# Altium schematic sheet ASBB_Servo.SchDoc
size A4
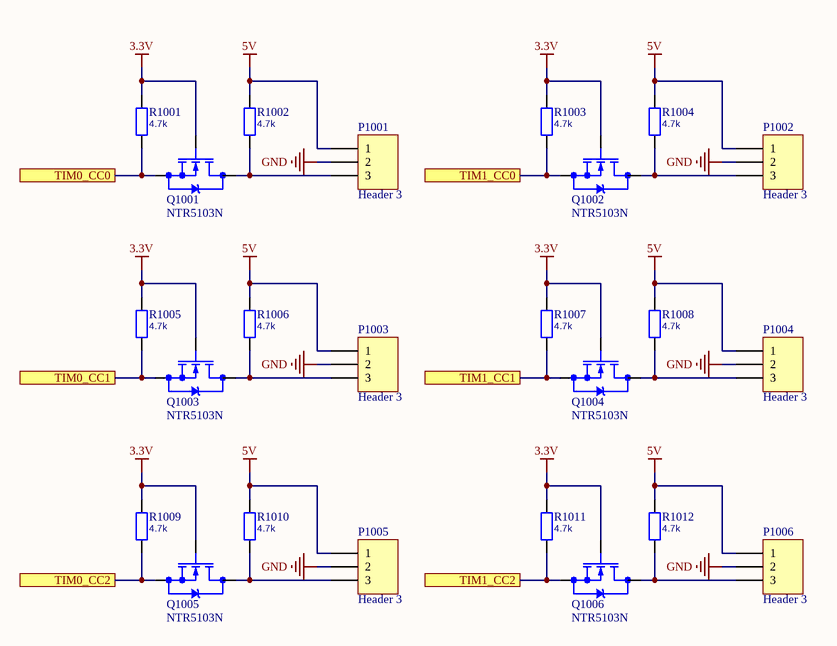
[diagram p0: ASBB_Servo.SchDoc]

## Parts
P1001  Header 3  [HDR1X3]
P1002  Header 3  [HDR1X3]
P1003  Header 3  [HDR1X3]
P1004  Header 3  [HDR1X3]
P1005  Header 3  [HDR1X3]
P1006  Header 3  [HDR1X3]
Q1001  NTR5103N  [SOT23]
Q1002  NTR5103N  [SOT23]
Q1003  NTR5103N  [SOT23]
Q1004  NTR5103N  [SOT23]
Q1005  NTR5103N  [SOT23]
Q1006  NTR5103N  [SOT23]
R1001  4.7k  [0603]
R1002  4.7k  [0603]
R1003  4.7k  [0603]
R1004  4.7k  [0603]
R1005  4.7k  [0603]
R1006  4.7k  [0603]
R1007  4.7k  [0603]
R1008  4.7k  [0603]
R1009  4.7k  [0603]
R1010  4.7k  [0603]
R1011  4.7k  [0603]
R1012  4.7k  [0603]

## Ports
TIM0_CC0, TIM0_CC1, TIM0_CC2, TIM1_CC0, TIM1_CC1, TIM1_CC2

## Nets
3.3V: Q1001.1(G) Q1002.1(G) Q1003.1(G) Q1004.1(G) Q1005.1(G) Q1006.1(G) R1001.2 R1003.2 R1005.2 R1007.2 R1009.2 R1011.2
5V: P1001.1 P1002.1 P1003.1 P1004.1 P1005.1 P1006.1 R1002.2 R1004.2 R1006.2 R1008.2 R1010.2 R1012.2
GND: P1001.2 P1002.2 P1003.2 P1004.2 P1005.2 P1006.2
TIM0_CC0: Q1001.2(S) R1001.1 ; port TIM0_CC0
TIM0_CC1: Q1003.2(S) R1005.1 ; port TIM0_CC1
TIM0_CC2: Q1005.2(S) R1009.1 ; port TIM0_CC2
TIM1_CC0: Q1002.2(S) R1003.1 ; port TIM1_CC0
TIM1_CC1: Q1004.2(S) R1007.1 ; port TIM1_CC1
TIM1_CC2: Q1006.2(S) R1011.1 ; port TIM1_CC2
NetP1001_3: P1001.3 Q1001.3(D) R1002.1
NetP1002_3: P1002.3 Q1002.3(D) R1004.1
NetP1003_3: P1003.3 Q1003.3(D) R1006.1
NetP1004_3: P1004.3 Q1004.3(D) R1008.1
NetP1005_3: P1005.3 Q1005.3(D) R1010.1
NetP1006_3: P1006.3 Q1006.3(D) R1012.1

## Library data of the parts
P1001-P1006 = Header 3: Header, 3-Pin
Q1001-Q1006 = NMOS SOT23: N-Channel MOSFET SOT23
R1001-R1012 = Resistor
